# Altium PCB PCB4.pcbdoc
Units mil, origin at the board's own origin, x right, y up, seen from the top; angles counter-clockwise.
Board outline 3707.89 x 4491.52 mil, 2 copper layers (Top Layer, Bottom Layer); 62 components, 49 nets, 252 pads, 122 vias.
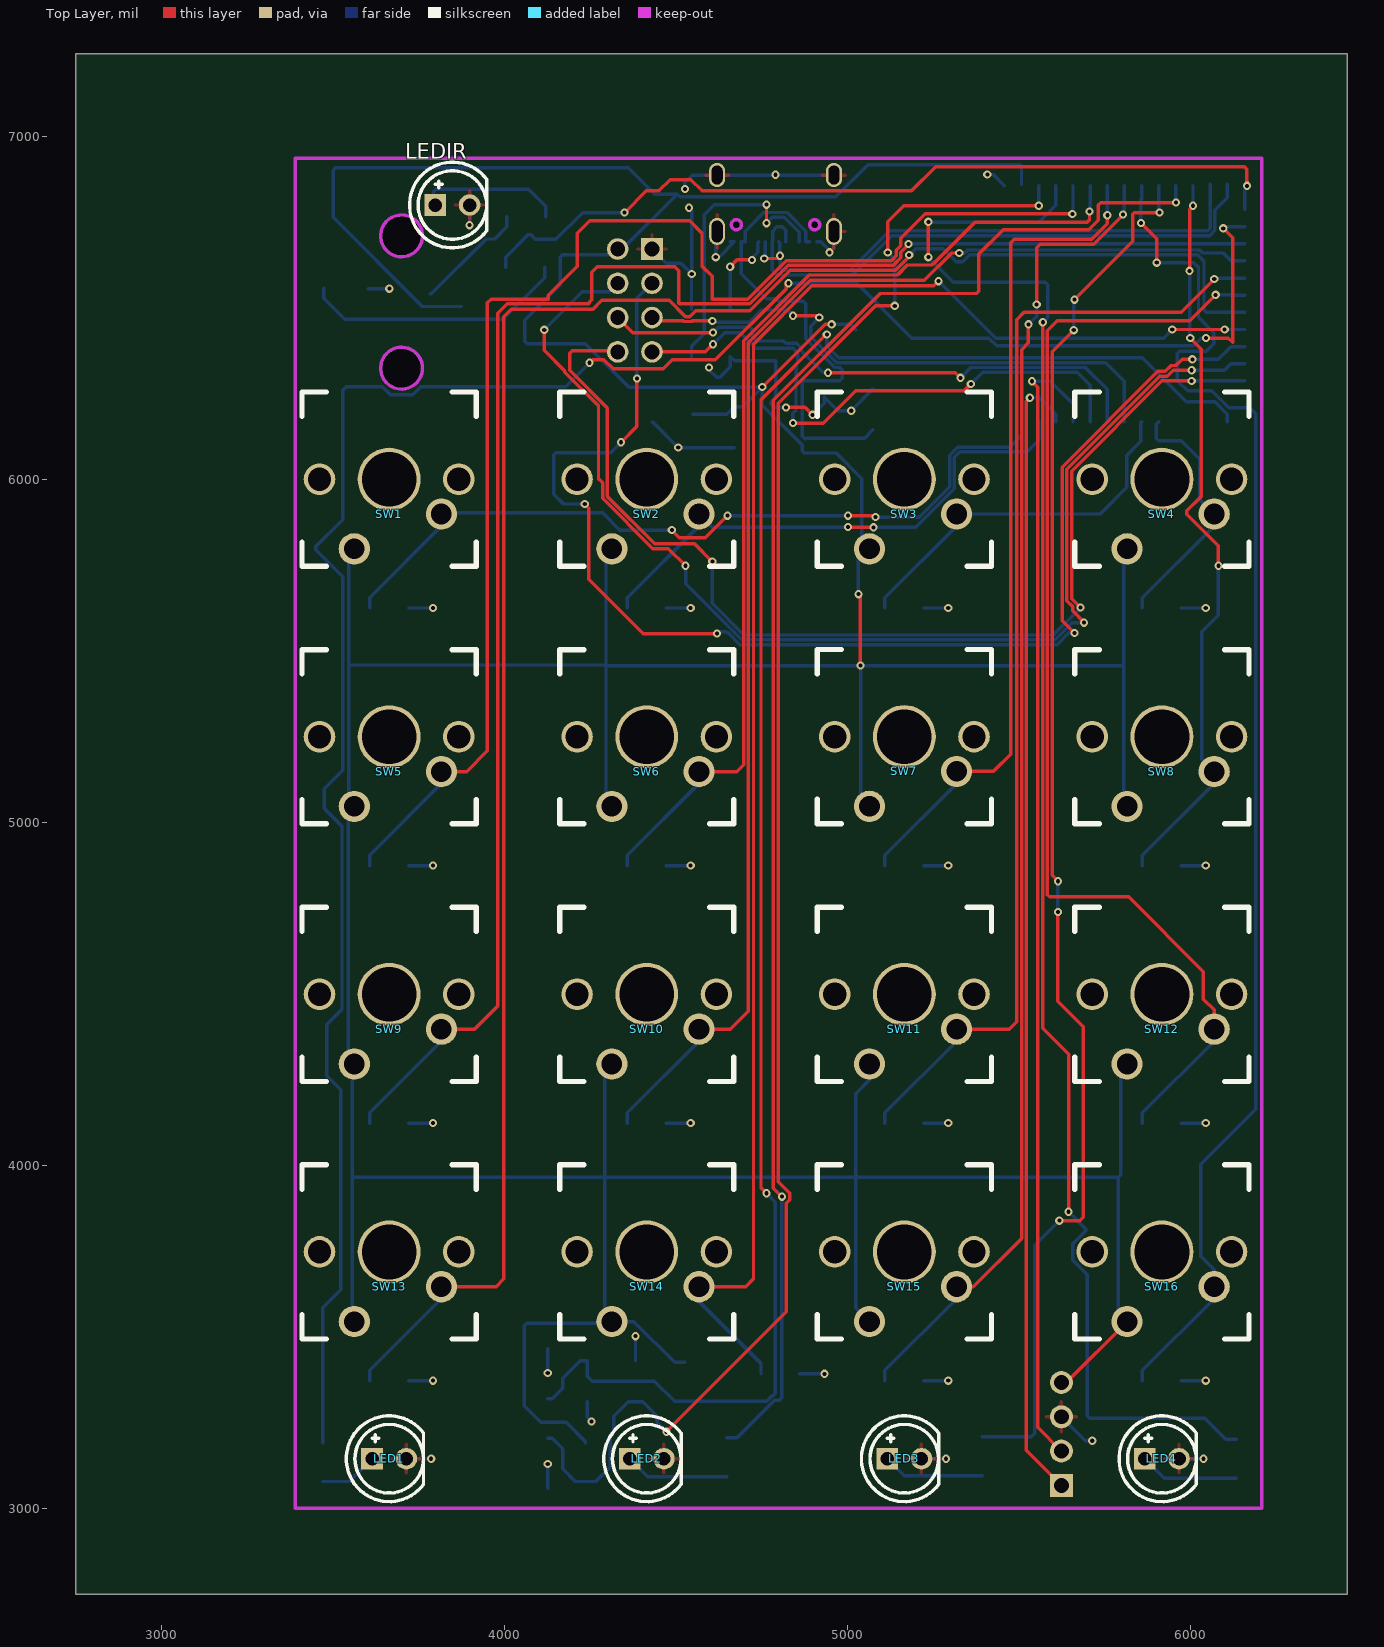
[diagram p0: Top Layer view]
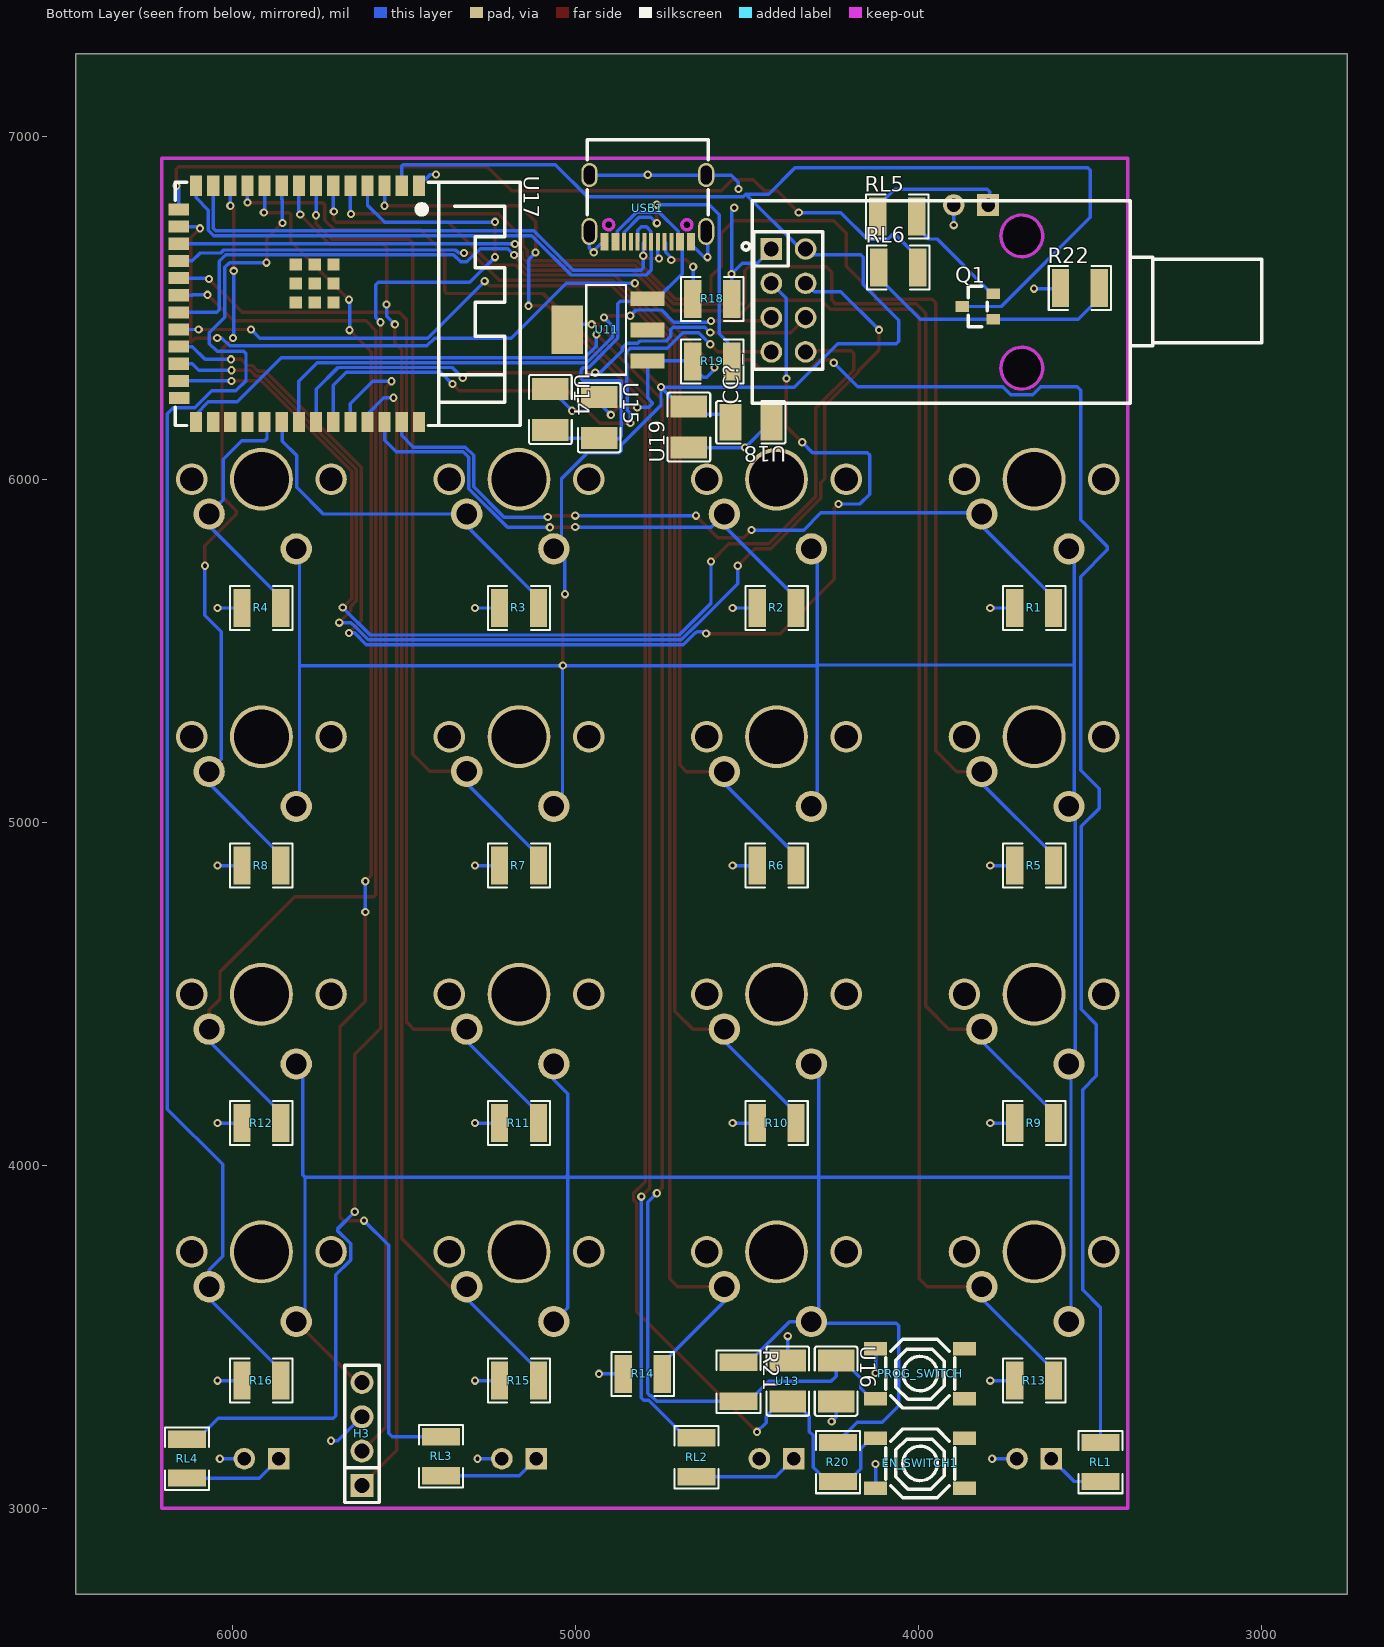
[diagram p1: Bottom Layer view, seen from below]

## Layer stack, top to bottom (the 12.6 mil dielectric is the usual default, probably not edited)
Top Layer: signal copper (thickness not stored)
Dielectric: dielectric 12.6, FR-4, Dk 4.8
Bottom Layer: signal copper (thickness not stored)

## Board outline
6457.89,2750 2750,2750 2750,7241.52 6457.89,7241.52

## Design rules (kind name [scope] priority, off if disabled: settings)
Clearance copperThickness1oz [All] p1: gap=7 ignorepadtopadclearanceinfootprint=FALSE except(4: Track-Track; 6: Track-SMDPad SMDPad-SMDPad Track-THPad SMDPad-THPad THPad-THPad Track-Via SMDPad-Via THPad-Via Via-Via Track-Fill SMDPad-Fill THPad-Fill Via-Fill Fill-Fill SMDPad-Region THPad-Region Via-Region Fill-Region Region-Region Track-Poly SMDPad-Poly THPad-Poly Via-Poly Fill-Poly Poly-Poly Track-Text SMDPad-Text THPad-Text Via-Text Fill-Text Region-Text Poly-Text Text-Text Track-Hole SMDPad-Hole THPad-Hole Via-Hole Fill-Hole Region-Hole Poly-Hole Text-Hole; 11.8: Track-Region Region-Poly Track-Sheet SMDPad-Sheet THPad-Sheet Via-Sheet Fill-Sheet Region-Sheet Poly-Sheet Text-Sheet Sheet-Hole)
Clearance copperThickness2oz [All] p1: gap=7 ignorepadtopadclearanceinfootprint=FALSE except(6: Track-SMDPad SMDPad-SMDPad Track-THPad SMDPad-THPad THPad-THPad Track-Via SMDPad-Via THPad-Via Via-Via Track-Fill SMDPad-Fill THPad-Fill Via-Fill Fill-Fill SMDPad-Region THPad-Region Via-Region Fill-Region Region-Region Track-Poly SMDPad-Poly THPad-Poly Via-Poly Fill-Poly Poly-Poly Track-Text SMDPad-Text THPad-Text Via-Text Fill-Text Region-Text Poly-Text Text-Text Track-Hole SMDPad-Hole THPad-Hole Via-Hole Fill-Hole Region-Hole Poly-Hole Text-Hole; 8: Track-Track; 11.8: Track-Region Region-Poly Track-Sheet SMDPad-Sheet THPad-Sheet Via-Sheet Fill-Sheet Region-Sheet Poly-Sheet Text-Sheet Sheet-Hole)
DiffPairsRouting differentialPair [All] p1: maxuncoupledlength=10 maxlimit=6 mostfreqgap=6 toplayer_minwidth=5 toplayer_prefwidth=10 toplayer_maxwidth=100 bottomlayer_minwidth=5 bottomlayer_prefwidth=10 bottomlayer_maxwidth=100
PasteMaskExpansion pasteMaskExpansion [All] p1:
PlaneConnect innerPlane [All] p1: planeconnectstyle=Relief reliefexpansion=20 reliefentries=4 reliefconductorwidth=10 reliefairgap=10
PolygonConnect copperRegion [All] p1: connectstyle=Relief reliefentries=4 reliefconductorwidth=10 polygonreliefangle="90 Angle" airgapwidth=10
RoutingVias viaSize [All] p1: viastyle="Through Hole" holewidth=12.0078 minholewidth=11.811 maxholewidth=248.0314 width=24.0158 minwidth=19.685 maxwidth=393.7008
SolderMaskExpansion solderMaskExpansion [All] p1: useseparateexpansions=TRUE expansion=2 expansionbottom=2
Width copperThickness1oz [All] p1: maxlimit=100 minlimit=5 preferedwidth=10
Width copperThickness2oz [All] p1: maxlimit=100 minlimit=8 preferedwidth=10

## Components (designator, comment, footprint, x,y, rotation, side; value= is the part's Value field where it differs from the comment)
CC?_ "CC1101 Module" CC1101-BOARS 3949.53,6520.97 r90 bottom
EN_SWITCH1 "TS-1187A-B-A-B" SW-SMD_4P-L5.1-W5.1-P3.70-LS6.5-TL-2 3995.89,3130.97 r180 bottom
H3 "HDR-M_2.54_1x4P" HDR-TH_4P-P2.54-V-M 5623.89,3216.97 r90 bottom
LED1 "LED_TH-R_5mm" LED-TH_BD5.8-P2.54-FD 3663.48,3144.65 r0 top
LED2 "LED_TH-R_5mm" LED-TH_BD5.8-P2.54-FD 4414.66,3144.65 r0 top
LED3 "LED_TH-R_5mm" LED-TH_BD5.8-P2.54-FD 5165.84,3144.65 r0 top
LED4 "LED_TH-R_5mm" LED-TH_BD5.8-P2.54-FD 5917.02,3144.65 r0 top
LEDIR "LED_TH-R_5mm" LED-TH_BD5.8-P2.54-FD 3847.89,6800.97 r0 top
PROG_SWITCH "TS-1187A-B-A-B" SW-SMD_4P-L5.1-W5.1-P3.70-LS6.5-TL-2 3995.89,3392.97 r180 bottom
Q1 "S8050_NPN" SOT-23_L2.9-W1.3-P1.90-LS2.4-BR 3827.89,6504.97 r180 bottom
R1 "1210W2F1022T5E" R1210 3663.48,5625.79 r180 bottom
R2 "1210W2F1022T5E" R1210 4414.66,5625.79 r180 bottom
R3 "1210W2F1022T5E" R1210 5165.84,5625.79 r180 bottom
R4 "1210W2F1022T5E" R1210 5917.02,5625.79 r180 bottom
R5 "1210W2F1022T5E" R1210 3663.48,4874.61 r180 bottom
R6 "1210W2F1022T5E" R1210 4414.66,4874.61 r180 bottom
R7 "1210W2F1022T5E" R1210 5165.84,4874.61 r180 bottom
R8 "1210W2F1022T5E" R1210 5917.02,4874.61 r180 bottom
R9 "1210W2F1022T5E" R1210 3663.48,4123.43 r180 bottom
R10 "1210W2F1022T5E" R1210 4414.66,4123.43 r180 bottom
R11 "1210W2F1022T5E" R1210 5165.84,4123.43 r180 bottom
R12 "1210W2F1022T5E" R1210 5917.02,4123.43 r180 bottom
R13 "1210W2F1022T5E" R1210 3663.48,3372.24 r180 bottom
R14 "1210W2F1022T5E" R1210 4804.66,3392.24 r180 bottom
R15 "1210W2F1022T5E" R1210 5165.84,3372.24 r180 bottom
R16 "1210W2F1022T5E" R1210 5917.02,3372.24 r180 bottom
R18 "SCR1210J5K1" R1210 4601.89,6526.97 r0 bottom
R19 "SCR1210J5K1" R1210 4601.89,6344.97 r180 bottom
R20 "1210W2F1022T5E" R1210 4235.89,3134.97 r90 bottom
R21 "1210W2F1022T5E" R1210 4525.89,3368.97 r270 bottom
R22 "1210W2F1022T5E" R1210 3529.89,6558.97 r180 bottom
RL1 "RTT12331JTP" R1210 3469.89,3134.97 r90 bottom
RL2 "RTT12331JTP" R1210 4647.89,3148.97 r90 bottom
RL3 "RTT12331JTP" R1210 5393.1,3152.12 r90 bottom
RL4 "RTT12331JTP" R1210 6133.89,3144.97 r90 bottom
RL5 "RTT12331JTP" R1210 4062.88,6767.19 r180 bottom
RL6 "RTT12331JTP" R1210 4059.89,6618.97 r180 bottom
SW1 "CHERRY-MX-LED" CHERRYMX 3663.48,6001.38 r0 top
SW2 "CHERRY-MX-LED" CHERRYMX 4414.66,6001.38 r0 top
SW3 "CHERRY-MX-LED" CHERRYMX 5165.84,6001.38 r0 top
SW4 "CHERRY-MX-LED" CHERRYMX 5917.02,6001.38 r0 top
SW5 "CHERRY-MX-LED" CHERRYMX 3663.48,5250.2 r0 top
SW6 "CHERRY-MX-LED" CHERRYMX 4414.66,5250.2 r0 top
SW7 "CHERRY-MX-LED" CHERRYMX 5165.84,5250.59 r0 top
SW8 "CHERRY-MX-LED" CHERRYMX 5917.02,5250.2 r0 top
SW9 "CHERRY-MX-LED" CHERRYMX 3663.48,4499.02 r0 top
SW10 "CHERRY-MX-LED" CHERRYMX 4414.66,4499.02 r0 top
SW11 "CHERRY-MX-LED" CHERRYMX 5165.84,4499.02 r0 top
SW12 "CHERRY-MX-LED" CHERRYMX 5917.02,4499.02 r0 top
SW13 "CHERRY-MX-LED" CHERRYMX 3663.48,3747.83 r0 top
SW14 "CHERRY-MX-LED" CHERRYMX 4414.66,3747.83 r0 top
SW15 "CHERRY-MX-LED" CHERRYMX 5165.84,3747.83 r0 top
SW16 "CHERRY-MX-LED" CHERRYMX 5917.02,3747.83 r0 top
U11 "AMS1117-3.3_C6186" SOT-223-3_L6.5-W3.4-P2.30-LS7.0-BR 4907.78,6436.97 r180 bottom
U13 "CC1210KKX7R9BB105" C1210 4381.89,3370.97 r90 bottom
U14 "CC1210KKX7R9BB105" C1210 5074.15,6204.71 r270 bottom
U15 "CC1210KKX7R9BB105" C1210 4932.15,6180.71 r270 bottom
U16 "CC1210KKX7R9BB105" C1210 4241.08,3370.76 r270 bottom
U17 "ESP32-S3-WROOM-1-N8R8" WIRELM-SMD_ESP32-S3-WROOM-1 5807.89,6512.97 r270 bottom
U18 "CC1210KKX7R9BB105" C1210 4489.63,6167.23 r0 bottom
U19 "CC1210KKX7R9BB105" C1210 4670.1,6153.26 r90 bottom
USB1 "USB-TYPE-C-018" USB-C_SMD-TYPE-C-31-M-12 4790.25,6790.97 r0 bottom

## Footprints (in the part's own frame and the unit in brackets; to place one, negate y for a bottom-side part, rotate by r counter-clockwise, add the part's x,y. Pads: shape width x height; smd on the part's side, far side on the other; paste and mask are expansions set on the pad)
C1210 [mm]
  rect 1.635x2.7 smd: 1(-1.517,0) 2(1.517,0)
  silkscreen extent -2.56,-1.58 2.56,1.58
CC1101-BOARS [mm]
  rect 1.6x1.6 hole 1.1: 1(3.856,12.203)
  round 1.6 hole 1.1: 2(3.856,9.663) 3(1.316,12.203) 4(1.316,9.663) 5(-1.224,12.203) 6(-1.224,9.663) 7(-3.764,12.203) 8(-3.764,9.663)
  Multi-Layer board cut-out: -4.974,-4.8 -4.301,-4.954 -3.762,-5.384 -3.463,-6.005 -3.463,-6.695 -3.762,-7.317 -4.302,-7.747 -4.974,-7.9 -4.974,-7.9 -5.647,-7.747 -6.186,-7.317 -6.485,-6.695 -6.485,-6.005 -6.186,-5.384 -5.647,-4.954 -4.974,-4.8
  Multi-Layer board cut-out: 4.826,-4.8 5.499,-4.954 6.038,-5.384 6.337,-6.005 6.337,-6.695 6.038,-7.317 5.499,-7.747 4.826,-7.9 4.826,-7.9 4.154,-7.747 3.614,-7.317 3.315,-6.695 3.315,-6.005 3.614,-5.384 4.154,-4.954 4.826,-4.8
  Multi-Layer keep-out circle w0.254: c-4.974,-6.35 r1.55
  Multi-Layer keep-out circle w0.254: c4.826,-6.35 r1.55
  silkscreen extent -7.57,-24.12 7.43,14.36
CHERRYMX [mil]
  round 91.4 hole 60: 1(-101.6,-203.2) 2(152.4,-101.6)
  round 92.1 hole 68: 3(203.2,0) 4(-203.2,0)
  round 183.5 hole 159.6: 5(0,0)
  silkscreen extent -254,-254 254,254
HDR-TH_4P-P2.54-V-M [mm]
  rect 1.7x1.7 hole 1.1: 1(-3.81,0)
  round 1.7 hole 1.1: 2(-1.27,0) 3(1.27,0) 4(3.81,0)
  silkscreen extent -5.08,-1.27 5.08,1.27
LED-TH_BD5.8-P2.54-FD [mm]
  rect 1.6x1.6 hole 1: 1(-1.27,0)
  round 1.6 hole 1: 2(1.27,0)
  silkscreen extent -3.17,-3.17 2.54,3.17
R1210 [mil]
  rect 50.49x110.55 smd: 1(-56.74,0) 2(56.74,0)
  silkscreen extent -91,-64 91,64
SOT-23_L2.9-W1.3-P1.90-LS2.4-BR [mm]
  rect 1x0.8 smd: 1(1.15,-0.95) 2(1.15,0.95) 3(-1.15,0)
  silkscreen extent -0.7,-1.5 0.7,1.5
SOT-223-3_L6.5-W3.4-P2.30-LS7.0-BR [mm]
  rect 2.5x1.1 smd: 1(2.97,-2.3) 2(2.97,0) 3(2.97,2.3)
  rect 2.34x3.6 smd: 4(-2.97,0)
  silkscreen extent -1.57,-3.33 1.37,3.33
SW-SMD_4P-L5.1-W5.1-P3.70-LS6.5-TL-2 [mm]
  rect 1.7x1 smd: 1(-3.3,1.85) 2(3.3,1.85) 3(-3.3,-1.85) 4(3.3,-1.85)
  silkscreen extent -2.55,-2.55 2.55,2.55
USB-C_SMD-TYPE-C-31-M-12 [mm]
  oval 1.2x2 hole 0.8 slot 1.6 at 90 deg: 0(-4.325,1.706) 1(4.325,1.706)
  oval 1.2x1.8 hole 0.8 slot 1.4 at 90 deg: 2(4.325,-2.474) 3(-4.325,-2.474)
  rect 0.3x1.3 smd: A1(-3.35,2.474) A4(-2.55,2.474) A5(-1.25,2.474) A6(-0.25,2.474) A7(0.25,2.474) A8(1.25,2.474) A9(2.55,2.474) A12(3.35,2.474) B1(3.05,2.474) B4(2.25,2.474) B5(1.75,2.474) B6(0.75,2.474) B7(-0.75,2.474) B8(-1.75,2.474) B9(-2.25,2.474) B12(-3.05,2.474)
  Multi-Layer board cut-out: -2.525,1.206 -2.577,1.02 -2.714,0.884 -2.9,0.835 -3.086,0.884 -3.223,1.02 -3.275,1.206 -3.275,1.206 -3.223,1.391 -3.086,1.527 -2.9,1.577 -2.714,1.527 -2.577,1.391 -2.525,1.206
  Multi-Layer board cut-out: 3.275,1.206 3.223,1.02 3.086,0.884 2.9,0.835 2.714,0.884 2.577,1.02 2.525,1.206 2.525,1.206 2.577,1.391 2.714,1.527 2.9,1.577 3.086,1.527 3.223,1.391 3.275,1.206
  Multi-Layer keep-out circle w0.254: c-2.9,1.206 r0.375
  Multi-Layer keep-out circle w0.254: c2.9,1.206 r0.375
  silkscreen extent -4.47,-5.09 4.47,0.49
WIRELM-SMD_ESP32-S3-WROOM-1 [mm]
  rect 1.5x0.9 smd: 1(-8.75,8.895) 2(-8.75,7.625) 3(-8.75,6.355) 4(-8.75,5.085) 5(-8.75,3.815) 6(-8.75,2.545) 7(-8.75,1.275) 8(-8.75,0.005) 9(-8.75,-1.265) 10(-8.75,-2.535) 11(-8.75,-3.805) 12(-8.75,-5.075) 13(-8.75,-6.345) 14(-8.75,-7.615) 27(8.75,-7.615) 28(8.75,-6.345) 29(8.75,-5.075) 30(8.75,-3.805) 31(8.75,-2.535) 32(8.75,-1.265) 33(8.75,0.005) 34(8.75,1.275) 35(8.75,2.545) 36(8.75,3.815) 37(8.75,5.085) 38(8.75,6.355) 39(8.75,7.625) 40(8.75,8.895)
  rect 0.9x1.5 smd: 15(-6.985,-8.895) 16(-5.715,-8.895) 17(-4.445,-8.895) 18(-3.175,-8.895) 19(-1.905,-8.895) 20(-0.635,-8.895) 21(0.635,-8.895) 22(1.905,-8.895) 23(3.175,-8.895) 24(4.445,-8.895) 25(5.715,-8.895) 26(6.985,-8.865)
  rect 0.9x0.9 smd: 41(-2.9,-0.225) 41(-2.9,1.175) 41(-2.9,2.575) 41(-1.5,-0.225) 41(-1.5,1.175) 41(-1.5,2.575) 41(-0.1,-0.225) 41(-0.1,1.175) 41(-0.1,2.575)
  silkscreen extent -9,-9.14 9.02,16.39

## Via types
v1: diameter 24.02, hole 12.01, Top Layer to Bottom Layer, 122 vias

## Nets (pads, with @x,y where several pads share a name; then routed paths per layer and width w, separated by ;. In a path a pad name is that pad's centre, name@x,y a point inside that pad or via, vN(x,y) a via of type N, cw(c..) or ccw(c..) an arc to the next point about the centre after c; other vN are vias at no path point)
3.3V: CC?_.2 H3.4 Q1.3 R20.2 R21.1 SW1.1 SW2.1 SW3.1 SW4.1 SW5.1 SW6.1 SW7.1 SW8.1 SW9.1 SW10.1 SW11.1 SW12.1 SW13.1 SW14.1 SW15.1 SW16.1 U11.4 U17.2 U18.2 U19.2 | length 18106.2
  Top Layer w10: v1(4751.67,6269.9) 4934.74,6452.97 v1(4953.89,6452.97) ; v1(5031.89,5666.02) 5037.89,5660.02 v1(5037.89,5457.75) ; H3.4 5637.76,3366.97 SW16.1
  Bottom Layer w10: SW13.1 3555.89,3550.63 3555.89,3966.07 ; SW1.1 3545.89,5782.19 3545.89,5460.97 ; Q1.3 3759.89,6504.97 3499.89,6764.97 3499.89,6902.97 3506.96,6910.04 4360.82,6910.04 4437.89,6832.97 4503.89,6832.97 ; R20.2 4235.89,3194.97 4179.89,3250.97 4105.89,3250.97 4057.89,3298.97 4057.89,3532.97 4064.96,3540.04 4308.47,3540.04 SW14.1 ; SW10.1 4291.57,4274.32 4291.57,3966.07 ; SW6.1 4295.89,5064.17 4295.89,5460.97 ; SW2.1 4295.89,5781.01 4295.89,5460.97 ; R21.1 4495.86,3425.71 4376.93,3544.63 SW14.1 ; U18.2@4549.37,6191.23 4648.33,6191.23 U19.2 4694.77,6213 v1(4751.67,6269.9) ; v1(4953.89,6452.97) 5008.71,6452.97 U11.4 ; v1@5031.89,5457.9 4298.96,5457.9 4295.89,5460.97 ; v1(5031.89,5666.02) 5031.89,5765.83 SW3.1 5041.89,5820.53 5041.89,6002.79 4966.88,6077.8 4874.45,6077.8 4868.02,6084.23 4868.02,6101.02 4751.67,6217.37 v1(4751.67,6269.9) ; SW15.1 5023.89,3584.99 5023.89,3966.07 4291.57,3966.07 ; SW11.1 5064.24,4249.32 5023.89,4208.97 5023.89,3973.14 5030.96,3966.07 5789.89,3966.07 ; SW7.1 5038.96,5072.67 5038.96,5457.9 5801.89,5457.9 5805.89,5461.9 ; U17.2@5507.69,6861.46 5507.69,6915.16 5503.89,6918.97 5059.89,6918.97 4965.95,6825.03 4511.83,6825.03 4503.89,6832.97 ; SW16.1 5789.89,3570.17 5789.89,3966.07 ; SW12.1 5796.96,4277.35 5796.96,3973.14 5789.89,3966.07 ; SW8.1 5805.89,5056.53 5805.89,5461.9 ; SW4.1@5815.89,5798.18 5805.89,5788.18 5805.89,5461.9 ; 3545.89,5460.97 3545.89,5062.99 SW5.1 3543.89,5029.01 3543.89,4313.81 SW9.1 3555.89,4289.83 3555.89,3966.07 ; 3545.89,5460.97 3547.4,5459.46 4294.38,5459.46 4295.89,5460.97 ; 3555.89,3966.07 4291.57,3966.07 ; 4291.57,3966.07 4291.57,3566.13 SW14.1 ; 4503.89,6832.97 4343.7,6672.78 CC?_.2 4313.22,6656.04 4168.96,6656.04 4161.89,6648.97 4161.89,6568.17 4058.82,6465.1 4058.82,6404.04 4065.89,6396.97 4235.89,6396.97 4362.96,6269.9 v1(4751.67,6269.9)
5V: U11.3 U14.2 U15.2 USB1.A4 USB1.A9 USB1.B4 USB1.B9 | length 1396.4
  Bottom Layer w10: USB1.A9 USB1.B4 4878.83,6724.44 4824.22,6779.05 4756.28,6779.05 4701.67,6724.44 USB1.B9 USB1.A4 4689.86,6600.95 4763.3,6527.52 U11.3 4798.34,6520.04 4870.82,6520.04 4877.89,6512.97 4877.89,6413.09 4878.88,6412.1 4878.88,6410.69 4962.49,6327.09 4977.77,6327.09 4984.96,6319.9 4984.96,6296.02 4977.89,6288.95 4868.02,6288.95 4868.02,6126.97 4875.09,6119.9 4878.96,6119.9 4880.03,6120.97 U15.2 5050.15,6120.97 U14.2
$1N17024: LED1.1 RL1.1 | length 171.1
  Bottom Layer w10: RL1.1 3547.06,3078.23 LED1.1
$1N17244: LED2.1 RL2.1 | length 304.9
  Bottom Layer w10: LED2.1 4417.09,3092.23 RL2.1
$1N17270: LED3.1 RL3.1 | length 297.7
  Bottom Layer w10: LED3.1 5165.12,3095.38 RL3.1
$1N17296: LED4.1 RL4.1 | length 290.2
  Bottom Layer w10: LED4.1 5923.45,3088.23 RL4.1
$1N41929: 
$1N42156: R19.2 USB1.B5 | length 825.7
  Top Layer w10: v1(4763.89,6747.98) v1(4763.89,6802.04)
  Bottom Layer w10: R19.2@4545.15,6358.97 4545.15,6389 4581.89,6425.74 4581.89,6772.97 4610.96,6802.04 v1(4763.89,6802.04) ; v1(4763.89,6747.98) 4780.95,6765.03 4815.83,6765.03 4859.15,6721.71 USB1.B5
$1N52929: LEDIR.1 RL5.1 | length 421.4
  Bottom Layer w10: LEDIR.1 3797.89,6824.83 3792.82,6829.9 3792.82,6839.9 3799.89,6846.97 4069.87,6846.97 4119.62,6797.22 RL5.1
$1N52957: Q1.2 RL5.2 | length 334.2
  Bottom Layer w10: Q1.2 3786.55,6542.37 3946.1,6701.92 3970.89,6701.92 4006.14,6737.16 RL5.2
$1N53158: Q1.1 R22.2 RL6.1 | length 779.2
  Bottom Layer w10: R22.2 3473.15,6528.94 3534.52,6467.57 Q1.1 3995.26,6467.57 4116.63,6588.94 RL6.1
EN: EN_SWITCH1.1 R20.1 U13.1 U17.3 | length 5051.1
  Top Layer w10: v1(4471.89,3222.97) 4821.89,3572.97 4821.89,3889.38 4831.95,3899.44 4831.95,3918.49 4797.91,3952.54 4797.91,6222.98 5081.89,6506.97 v1(5137.89,6506.97) ; v1(5117.49,6662.51) 5117.49,6752.57 5163.89,6798.97 v1(5557.89,6798.97)
  Bottom Layer w10: EN_SWITCH1.1 4139.59,3203.81 4169.27,3174.13 4169.27,3114.82 4205.86,3078.23 R20.1 4265.92,3078.23 4307.89,3120.2 4307.89,3212.97 4318.74,3223.82 4318.74,3269.05 4360.93,3311.23 U13.1 4402.85,3311.23 4445.04,3269.05 4445.04,3249.82 v1(4471.89,3222.97) ; v1(5117.49,6662.51) 5137.89,6642.1 v1(5137.89,6506.97) ; U17.3 5557.89,6857.26 v1(5557.89,6798.97)
GND: CC?_.1 EN_SWITCH1.3 H3.3 LED1.2 LED2.2 LED3.2 LED4.2 LEDIR.2 PROG_SWITCH.1 R1.1 R2.1 R3.1 R4.1 R5.1 R6.1 R7.1 R8.1 R9.1 R10.1 R11.1 R12.1 R13.1 R14.1 R15.1 R16.1 R18.1 R19.1 R22.1 U11.1 U13.2 U14.1 U15.1 U16.2 U17.1 U18.1 U19.1 USB1.0 USB1.1 USB1.2 USB1.3 USB1.A1 USB1.A12 USB1.B1 USB1.B12 | length 4168.7
  Top Layer w10: v1(4820.9,6210.6) 4876.26,6210.6 v1(4897.89,6188.97)
  Bottom Layer w10: R22.1@3602.63,6556.97 v1(3663.89,6556.97) ; LED1.2 v1(3785.89,3144.65) ; R13.1 v1(3791.53,3372.24) ; R9.1 v1(3791.53,4123.43) ; R5.1 v1(3791.53,4874.61) ; R1.1 v1(3791.53,5625.79) ; v1(3897.89,6742.15) LEDIR.2 ; EN_SWITCH1.3 v1(4125.81,3129.43) ; v1(4125.81,3394.5) PROG_SWITCH.1 ; U16.2 4241.08,3265.78 v1(4253.89,3252.97) ; U13.2 v1(4381.89,3502.02) ; U18.1 4432.93,6167.23 v1(4506.63,6093.52) U19.1 ; CC?_.1 4471.45,6631.29 4514.58,6631.29 v1(4545.89,6599.98) ; R10.1 v1(4542.71,4123.43) ; R6.1 v1(4542.71,4874.61) ; R2.1 v1(4542.71,5625.79) ; v1(4525.89,6848.02) 4525.89,6866.97 4547.3,6888.37 USB1.3 4789.28,6888.37 v1(4790.25,6889.34) 4791.22,6888.37 USB1.2 ; v1(4537.89,6792.97) 4545.89,6784.97 v1(4545.89,6599.98) ; R18.1@4545.15,6496.97 4545.15,6599.24 v1(4545.89,6599.98) ; v1(4595.94,6326.97) 4595.94,6321.14 4618.39,6298.69 4628.39,6298.69 4658.63,6328.94 4658.63,6358.97 4671.18,6346.42 U11.1 4790.86,6238.61 4776.9,6224.65 4776.9,6221.96 4787.89,6210.97 4820.53,6210.97 v1(4820.9,6210.6) ; USB1.0 4615.89,6719.73 v1(4615.89,6648.97) 4625.58,6648.97 USB1.B12 USB1.A1 ; R14.1 v1(4932.71,3392.24) ; v1(4897.89,6188.97) 4932.15,6223.23 U15.1 4971.63,6200.97 v1(5011.03,6200.97) 5011.03,6201.32 U14.1 ; USB1.B1 USB1.A12 4947.89,6667.81 v1(4947.89,6662.97) 4960.53,6675.61 USB1.1 ; LED3.2 v1(5287.15,3144.65) ; R15.1 v1(5293.89,3372.24) ; R11.1 v1(5293.89,4123.43) ; R7.1 v1(5293.89,4874.61) ; R3.1 v1(5293.89,5625.79) ; v1(5407.89,6889.98) 5425.18,6889.98 U17.1 ; H3.3 5693.89,3196.97 v1(5713.89,3196.97) ; LED4.2 v1(6038.33,3144.65) ; R16.1 v1(6045.07,3372.24) ; R12.1 v1(6045.07,4123.43) ; R8.1 v1(6045.07,4874.61) ; R4.1 v1(6045.07,5625.79)
IO0: PROG_SWITCH.3 R21.2 U16.1 U17.27 | length 5304.6
  Top Layer w10: v1(4763.89,3918.97) 4747.89,3934.97 4747.89,6233.61 4937.25,6422.97 v1(4939.89,6422.97)
  Bottom Layer w10: PROG_SWITCH.3 4139.59,3320.13 4169.27,3349.81 4169.27,3379.65 4220.11,3430.49 U16.1 4241.08,3385.78 4255.89,3370.97 4437.12,3370.97 4495.86,3312.23 R21.2 4764.62,3312.23 4781.37,3328.98 4783.91,3328.98 4789.89,3334.97 4789.89,3892.97 v1(4763.89,3918.97) ; v1(4939.89,6422.97) 4939.89,6389.33 4974.1,6355.12 5859.74,6355.12 5987.89,6226.97 6071.89,6226.97 6107.69,6191.16 U17.27
IO1: R1.2 SW1.2 U17.39 | length 2303.4
  Top Layer w10: v1(4487.89,5852.97) 4509.89,5830.97 4585.89,5830.97 v1(4649.89,5894.97) ; v1(5001.89,5894.97) 5077.87,5894.97 v1(5081.87,5890.97)
  Bottom Layer w10: R1.2 3606.74,5655.82 3815.88,5864.96 SW1.2 3819.07,5902.97 4285.89,5902.97 4335.89,5852.97 v1(4487.89,5852.97) ; v1(4649.89,5894.97) v1(5001.89,5894.97) ; v1(5081.87,5890.97) 5209.45,5890.97 5297.87,5979.39 5297.87,6070.77 5322.08,6094.98 5473.73,6094.98 5507.69,6128.95 U17.39
IO2: R2.2 SW2.2 U17.38 | length 1579.9
  Top Layer w10: v1(5001.89,5861.78) 5075.08,5861.78 v1(5075.89,5860.97)
  Bottom Layer w10: R2.2 4357.92,5655.82 4567.06,5864.96 SW2.2 4605.27,5861.57 5001.68,5861.57 v1(5001.89,5861.78) ; v1(5075.89,5860.97) 5199.27,5860.97 5311.89,5973.59 5311.89,6064.97 5327.89,6080.97 5523.89,6080.97 5557.69,6114.77 U17.38
IO3: RL6.2 U17.15 | length 2463.9
  Top Layer w10: v1(4349.89,6778.97) 4412.88,6841.96 4449.89,6841.96 4482.9,6874.97 4543.36,6874.97 4576.37,6841.96 5186.88,6841.96 5257.89,6912.97 6157.89,6912.97 6164.96,6905.9 v1(6164.96,6856.97)
  Bottom Layer w10: RL6.2 4003.15,6649 4069.12,6714.97 4075.78,6714.97 4089.82,6700.93 4149.42,6700.93 4227.45,6778.97 v1(4349.89,6778.97) ; U17.15 6158.09,6850.09 v1(6164.96,6856.97)
IO4: RL4.2 U17.4 | length 4781.7
  Top Layer w10: v1(5235.89,6648.97) v1(5235.89,6751.98) ; 5568.95,6446.04 5568.95,4399.91 5644.82,4324.04 v1(5644.82,3864.97) ; v1@5569.89,6451.1 v1(5569.89,6458.97)
  Bottom Layer w10: v1(5235.89,6648.97) 5308.82,6576.04 5576.82,6576.04 5583.89,6568.97 5583.89,6472.97 v1(5569.89,6458.97) ; v1(5235.89,6751.98) 5236.9,6750.97 5557.89,6750.97 5607.69,6800.77 U17.4 ; v1(5644.82,3864.97) 5695.23,3814.56 5695.23,3809.9 5656.79,3771.46 5656.79,3724.21 5699.89,3681.11 5699.89,3270.04 5706.96,3262.97 6042.6,3262.97 6103.86,3201.71 RL4.2
IO5: R5.2 SW5.2 U17.5 | length 4092.5
  Top Layer w10: SW5.2 3889.52,5148.6 3949.89,5208.97 3949.89,6515.9 3960.67,6526.68 4127.04,6526.68 4127.04,6538.12 4211.89,6622.97 4211.89,6718.97 4247.89,6754.97 4539.89,6754.97 4575.89,6718.97 4575.89,6622.97 4605.89,6592.97 4605.89,6526.68 4709.44,6526.68 4821.76,6639 5128.46,6639 5141.96,6652.51 5141.96,6669.38 5154.9,6682.31 5154.9,6703.5 5226.37,6774.97 v1(5655.89,6774.97)
  Bottom Layer w10: R5.2 3606.74,4904.64 3815.88,5113.78 SW5.2 ; v1(5655.89,6774.97) 5657.69,6776.77 U17.5
IO6: R6.2 SW6.2 U17.6 | length 2991.3
  Top Layer w10: SW6.2 4677.52,5148.6 4696.93,5168.01 4696.93,6405.65 4888.23,6596.95 5145.87,6596.95 5174.9,6625.98 5245.41,6625.98 5248.41,6628.97 5249.89,6628.97 5371.89,6750.97 5698.86,6750.97 5705.89,6758 v1(5705.89,6782)
  Bottom Layer w10: R6.2 4357.92,4904.64 4567.06,5113.78 SW6.2 ; v1(5705.89,6782) 5707.69,6783.8 U17.6
IO7: R7.2 SW7.2 U17.7 | length 2447.2
  Top Layer w10: SW7.2 5425.91,5148.99 5475.89,5198.97 5475.89,6690.98 5485.89,6700.98 5712.08,6700.98 5757.89,6746.79 v1(5757.89,6770.97)
  Bottom Layer w10: R7.2 5109.1,4904.64 5318.24,5113.78 SW7.2 ; U17.7 5757.69,6771.16 v1(5757.89,6770.97)
IO8: R8.2 SW8.2 U17.12 | length 2173.9
  Top Layer w10: v1(5997.69,6608.97) 5997.69,6788.97 v1(6007.69,6798.97) ; v1(5999.69,6412.97) 6031.89,6380.77 6031.89,5950.97 5989.89,5908.97 5989.89,5898.97 6081.89,5806.97 v1@6081.89,5752.97
  Bottom Layer w10: R8.2 5860.28,4904.64 6069.42,5113.78 SW8.2 6033.89,5184.13 6033.89,5556.97 6081.89,5604.97 v1(6081.89,5748.97) ; v1(5997.69,6608.97) 5997.69,6414.97 v1(5999.69,6412.97) ; v1(6007.69,6798.97) U17.12
IO9: R9.2 SW9.2 U17.17 | length 5039.4
  Top Layer w10: SW9.2 3912.34,4397.42 3979.89,4464.97 3979.89,6484.97 4007.58,6512.66 4245.02,6512.66 4246.82,6514.46 4246.82,6517.9 4253.89,6524.97 4253.89,6604.97 4269.89,6620.97 4495.89,6620.97 4507.89,6608.97 4507.89,6514.89 4510.12,6512.66 4715.24,6512.66 4827.57,6624.98 5134.26,6624.98 5155.98,6646.7 5155.98,6663.57 5177.89,6685.48 v1(5177.89,6686.97)
  Bottom Layer w10: R9.2 3606.74,4153.45 3815.88,4362.59 SW9.2 ; v1(5177.89,6686.97) 5178.89,6687.97 U17.17
IO10: R10.2 SW10.2 U17.18 | length 4048.3
  Top Layer w10: SW10.2 4658.34,4397.42 4710.95,4450.03 4710.95,6399.85 4892.07,6580.97 5223.89,6580.97 5303.89,6660.97 v1(5325.89,6660.97)
  Bottom Layer w10: R10.2 4357.92,4153.45 4567.06,4362.59 SW10.2 ; v1(5325.89,6660.97) 5342.07,6660.97 5350.97,6669.86 6026.81,6669.86 6035.71,6660.97 6095.56,6660.97 6118.56,6637.97 U17.18
IO11: R11.2 SW11.2 U17.19 | length 3307.5
  Top Layer w10: SW11.2 5472.34,4397.42 5493.89,4418.97 5493.89,6466.97 5514.9,6487.98 5972.9,6487.98 v1(6069.89,6584.97)
  Bottom Layer w10: R11.2 5109.1,4153.45 5318.24,4362.59 SW11.2 ; v1(6069.89,6584.97) 6072.89,6587.97 U17.19
IO12: R12.2 SW12.2 U17.20 | length 3352.4
  Top Layer w10: SW12.2 6069.42,4453.43 6037.89,4484.97 6037.89,4564.97 5819.89,4782.97 5590.03,4782.97 5582.96,4790.04 5582.96,6434.04 5611.87,6462.95 5997.87,6462.95 v1(6073.89,6538.97)
  Bottom Layer w10: R12.2 5860.28,4153.45 6069.42,4362.59 SW12.2 ; v1(6073.89,6538.97) 6117.56,6538.97 6118.56,6537.97 U17.20
IO13: R13.2 SW13.2 U17.21 | length 5820.1
  Top Layer w10: SW13.2 3975.16,3646.23 3997.89,3668.97 3997.89,6474.97 4019.89,6496.97 4257.89,6496.97 4283.89,6522.97 4479.99,6522.97 4527.71,6475.26 4540.18,6475.26 4557.91,6492.98 4715.39,6492.98 4833.37,6610.97 5140.07,6610.97 5179.89,6650.79 v1(5179.89,6654.97)
  Bottom Layer w10: R13.2 3606.74,3402.27 3815.88,3611.41 SW13.2 ; v1(5179.89,6654.97) 5198.87,6673.95 5278.91,6673.95 5317.89,6634.97 5335.89,6634.97 5356.77,6655.85 6021.01,6655.85 6039.89,6636.97 6039.89,6495.04 6046.96,6487.97 U17.21
IO14: R14.2 SW14.2 U17.22 | length 4810.7
  Top Layer w10: SW14.2 4703.16,3646.23 4725.89,3668.97 4725.89,6394.97 4895.89,6564.97 5251.89,6564.97 v1(5265.89,6578.97) ; v1(5947.08,6437.97) v1(6100.09,6437.97)
  Bottom Layer w10: SW14.2 4567.06,3603.13 4747.92,3422.27 R14.2 ; v1(5265.89,6578.97) 5431.89,6412.97 5922.08,6412.97 v1(5947.08,6437.97) ; v1(6100.09,6437.97) U17.22
IO15: R15.2 SW15.2 U17.8 | length 3894.6
  Top Layer w10: SW15.2 5367.16,3646.23 5507.91,3786.98 5507.91,6378.99 5527.89,6398.98 v1(5527.89,6452.97) ; v1(5551.89,6510.97) 5551.89,6676.97 5561.89,6686.97 5717.89,6686.97 v1(5803.89,6772.97)
  Bottom Layer w10: R15.2 5109.1,3402.27 5318.24,3611.41 SW15.2 ; v1(5527.89,6452.97) 5551.89,6476.97 v1(5551.89,6510.97) ; v1(5803.89,6772.97) 5807.69,6776.77 U17.8
IO16: R16.2 SW16.2 U17.9 | length 4069
  Top Layer w10: v1(5855.89,6748.89) 5901.89,6702.89 v1(5901.89,6632.86)
  Bottom Layer w10: v1(5855.89,6748.89) 5855.89,6816.13 5857.69,6817.93 U17.9 ; R16.2 5860.28,3402.27 6069.42,3611.41 SW16.2 6069.42,3695.43 6029.89,3734.97 6029.89,4002.97 6191.08,4164.16 6191.08,6191.78 6173.59,6209.27 6111.89,6209.27 6062.19,6258.97 5991.89,6258.97 5961.89,6288.97 5961.89,6366.97 5968.96,6374.04 6046.02,6374.04 6068.88,6396.9 6068.88,6427.98 6023.71,6473.15 6023.71,6619.15 6010,6632.86 v1(5901.89,6632.86)
IO17: RL3.2 U17.10 | length 4100.4
  Top Layer w10: v1(5613.89,4738.97) 5613.89,4478.97 5687.89,4404.97 5687.89,3848.97 5677.89,3838.97 v1(5617.89,3838.97) ; v1(5613.89,4828.93) 5596.98,4845.84 5596.98,6373.05 v1(5659.89,6435.96) ; v1(5661.89,6524.97) 5831.89,6694.97 5831.89,6773.91 5836.95,6778.97 v1(5909.89,6778.97)
  Bottom Layer w10: RL3.2 5535.89,3208.86 5545.89,3218.86 5545.89,3766.97 v1(5617.89,3838.97) ; v1(5613.89,4738.97) v1(5613.89,4828.93) ; v1(5659.89,6435.96) 5659.89,6522.97 v1(5661.89,6524.97) ; U17.10 5907.69,6781.16 v1(5909.89,6778.97)
IO18: RL2.2 U17.11 | length 4680.1
  Top Layer w10: v1(4808.96,3908.97) 4783.89,3934.04 4783.89,6230.97 5095.89,6542.97 5375.89,6542.97 5382.96,6550.04 5382.96,6658.04 5453.89,6728.97 5703.89,6728.97 5731.89,6756.97 5731.89,6800.97 5738.96,6808.04 v1(5957.89,6808.04)
  Bottom Layer w10: RL2.2 4677.92,3205.71 4787.18,3314.97 4801.89,3314.97 4808.96,3322.04 v1(4808.96,3908.97) ; U17.11 5957.89,6857.26 v1(5957.89,6808.04)
IO19: U17.13 USB1.A7 USB1.B7 | length 1612.8
  Top Layer w10: v1(4757.42,6644.97) 4795.22,6644.97 v1(4803.4,6653.15)
  Bottom Layer w10: v1(4757.42,6644.97) 4760.72,6648.27 USB1.B7 ; USB1.A7 4802.89,6690.76 4802.89,6653.66 v1(4803.4,6653.15) 4803.4,6617.53 4809.96,6610.97 5007.89,6610.97 5122.82,6725.9 6050.62,6725.9 6057.69,6732.97 U17.13@6057.69,6861.46
IO20: U17.14 USB1.A6 USB1.B6 | length 1695.1
  Bottom Layer w10: USB1.B6 4819.89,6693.67 4819.89,6726.97 4809.89,6736.97 4793.91,6736.97 4781.89,6724.95 4781.89,6695.04 USB1.A6 4780.41,6611.5 4794.96,6596.95 5013.7,6596.95 5128.62,6711.88 6056.43,6711.88 6071.71,6727.16 6071.71,6785.95 6107.69,6821.93 U17.14@6107.69,6861.46
IO21: CC?_.3 U17.23 | length 3845.6
  Top Layer w10: v1(4233.89,5928.97) 4245.89,5916.97 4245.89,5708.97 4403.89,5550.97 v1(4619.89,5550.97) ; v1(4339.89,6108.97) 4385.89,6154.97 v1(4385.89,6294.97) ; v1(5661.89,5552.97) 5625.86,5589 5625.86,6036.58 5905.28,6316 5927.1,6316 5944.08,6332.98 5957.91,6332.98 5975.89,6350.97 v1(6005.89,6350.97)
  Bottom Layer w10: v1(4233.89,5928.97) 4171.89,5928.97 4142.82,5958.04 4142.82,6071.9 4149.89,6078.97 4309.89,6078.97 v1(4339.89,6108.97) ; v1(4385.89,6294.97) 4385.89,6528.71 CC?_.3 ; v1(4619.89,5550.97) 4625.89,5556.97 4645.89,5556.97 4649.89,5552.97 4652.25,5552.97 4686.28,5518.94 5611.5,5518.94 5645.53,5552.97 v1(5661.89,5552.97) ; v1(6005.89,6350.97) 6081.56,6350.97 6118.56,6387.97 U17.23
IO35: U17.28
IO36: U17.29
IO37: U17.30
IO38: R4.2 SW4.2 U17.31 | length 740.7
  Bottom Layer w10: R4.2 5860.28,5655.82 6069.42,5864.96 SW4.2 6027.89,5941.31 6027.89,6058.97 5973.89,6112.97 5907.89,6112.97 5900.82,6120.04 5900.82,6161.6 U17.31
IO39: R3.2 SW3.2 U17.32 | length 1097.9
  Bottom Layer w10: R3.2 5109.1,5655.82 5318.24,5864.96 SW3.2 5736.7,5899.78 5814.29,5977.37 5814.29,6070.44 5855.89,6112.04 5855.89,6166.67 U17.32
IO40: CC?_.5 U17.33 | length 1673.2
  Top Layer w10: CC?_.5 4439.77,6462.97 4520.96,6462.97 4521.9,6461.24 4545.98,6461.24 4547.71,6462.97 v1(4605.89,6462.97) ; v1(4841.43,6477.99) 4912.87,6477.99 v1(4917.89,6472.97)
  Bottom Layer w10: v1(4605.89,6462.97) 4609.89,6458.97 4713.89,6458.97 4749.8,6494.88 4824.54,6494.88 v1(4841.43,6477.99) ; v1(4917.89,6472.97) 4892.9,6447.98 4892.9,6416.5 4968.29,6341.1 5753.76,6341.1 5807.69,6287.16 U17.33
IO41: CC?_.6 U17.34 | length 1663.6
  Top Layer w10: CC?_.6 4373.77,6428.97 v1(4607.89,6428.97) ; v1(4943.38,6311.94) 5314.92,6311.94 v1(5329.89,6296.97)
  Bottom Layer w10: v1(4607.89,6428.97) 4623.87,6444.95 ; 4623.89,6444.95 4715.89,6444.95 4722.96,6437.88 4722.96,6417.9 4736.53,6404.33 4812.88,6404.33 4819.89,6397.32 4851.54,6397.32 4864.87,6383.99 4864.87,6376.35 4928.15,6313.07 4942.25,6313.07 v1(4943.38,6311.94) ; v1(5329.89,6296.97) 5360.01,6327.09 5693.77,6327.09 5757.69,6263.16 U17.34
IO42: CC?_.7 U17.35 | length 1733.7
  Top Layer w10: CC?_.7 4585.7,6372.78 v1(4607.89,6394.97) ; v1(4841.02,6165.05) 4929.98,6165.05 5023.89,6258.97 5339.89,6258.97 v1(5359.89,6278.97)
  Bottom Layer w10: v1(4607.89,6394.97) 4641.89,6428.97 4687.89,6428.97 4733.89,6382.97 4841.89,6382.97 4851.09,6373.77 4850.85,6370.54 4854.82,6366.58 4854.82,6341.9 4851.05,6338.13 4851.05,6274.9 4849.89,6273.73 4849.89,6202.97 4841.02,6194.1 v1(4841.02,6165.05) ; v1(5359.89,6278.97) 5393.99,6313.07 5669.79,6313.07 5707.69,6275.16 U17.35
IO45: U17.26
IO46: RL1.2 U17.16 | length 6505.4
  Top Layer w10: v1(4247.89,6340.97) 4256.88,6349.96 4289.44,6349.96 4316.43,6322.97 4462.66,6322.97 4489.65,6349.96 4614.88,6349.96 4820.98,6556.06 v1@4820.98,6575.88 ; v1(6045.89,6412.97) 6110.26,6412.97 6123.08,6400.16 6123.08,6705.78 v1(6095.89,6732.97)
  Bottom Layer w10: RL1.2 3469.89,3584.97 3521.89,3636.97 3521.89,4220.97 3481.89,4260.97 3481.89,4410.97 3525.89,4454.97 3525.89,4988.97 3473.89,5040.97 3473.89,5098.97 3527.89,5152.97 3527.89,5716.97 3449.89,5794.97 3449.89,5804.97 3527.89,5882.97 3527.89,6260.97 3537.89,6270.97 3643.62,6270.97 3667.29,6247.31 3731.77,6247.31 3755.43,6270.97 4177.89,6270.97 v1(4247.89,6340.97) ; v1(4827.89,6572.97) 5027.89,6572.97 5187.89,6412.97 5412.07,6412.97 5435.06,6389.98 6009.22,6389.98 6032.21,6412.97 v1(6045.89,6412.97) ; v1(6095.89,6732.97) 6100.89,6737.97 U17.16
IO47: CC?_.4 U17.24 | length 3572.5
  Top Layer w10: v1(4115.89,6436.97) 4115.89,6376.97 4175.87,6316.98 4175.87,6313.16 4273.89,6215.15 4273.89,6002.97 4285.87,5990.98 4285.87,5945.16 4432.08,5798.95 4477.91,5798.95 v1(4527.89,5748.97) ; v1(5689.89,5582.97) 5689.89,5584.45 5656.9,5617.44 5656.9,5630.14 5639.87,5647.16 5639.87,6030.77 5911.08,6301.98 5932.91,6301.98 5949.89,6318.97 v1(6003.89,6318.97)
  Bottom Layer w10: v1(4115.89,6436.97) 4226.82,6547.9 4305.07,6547.9 CC?_.4 ; v1(4527.89,5748.97) 4527.89,5696.97 4647.89,5576.97 4648.07,5576.97 4692.08,5532.95 5605.7,5532.95 5649.71,5576.97 5649.89,5576.97 5655.89,5582.97 v1(5689.89,5582.97) ; v1(6003.89,6318.97) 6099.56,6318.97 6118.56,6337.97 U17.24
IO48: CC?_.8 U17.25 | length 3281.8
  Top Layer w10: CC?_.8 4326.7,6376.04 4196.96,6376.04 4189.89,6368.97 4189.89,6318.97 4299.89,6208.97 4299.89,5950.97 4437.89,5812.97 4553.89,5812.97 v1(4605.89,5760.97) ; v1(5679.89,5626.97) 5653.89,5652.97 5653.89,6024.97 5916.89,6287.97 v1(6003.89,6287.97)
  Bottom Layer w10: v1(4605.89,5760.97) 4605.89,5638.97 4697.89,5546.97 5599.89,5546.97 v1(5679.89,5626.97) ; v1(6003.89,6287.97) U17.25
RX: H3.2 U17.36 | length 3355.4
  Top Layer w10: v1(5537.89,6286.97) 5554.88,6269.98 5554.88,3235.98 H3.2
  Bottom Layer w10: v1(5537.89,6286.97) 5591.89,6286.97 5657.69,6221.16 U17.36
TX: H3.1 U17.37 | length 3336.7
  Top Layer w10: v1(5531.89,6238.97) 5521.92,6229 5521.92,3168.94 H3.1
  Bottom Layer w10: v1(5531.89,6238.97) 5559.89,6238.97 5607.69,6191.16 U17.37
pads on no net: EN_SWITCH1.2 EN_SWITCH1.4 PROG_SWITCH.2 PROG_SWITCH.4 R18.2 SW1.3 SW1.4 SW1.5 SW2.3 SW2.4 SW2.5 SW3.3 SW3.4 SW3.5 SW4.3 SW4.4 SW4.5 SW5.3 SW5.4 SW5.5 SW6.3 SW6.4 SW6.5 SW7.3 SW7.4 SW7.5 SW8.3 SW8.4 SW8.5 SW9.3 SW9.4 SW9.5 SW10.3 SW10.4 SW10.5 SW11.3 SW11.4 SW11.5 SW12.3 SW12.4 SW12.5 SW13.3 SW13.4 SW13.5 SW14.3 SW14.4 SW14.5 SW15.3 SW15.4 SW15.5 SW16.3 SW16.4 SW16.5 U11.2 U17.40 U17.41 USB1.A5 USB1.A8 USB1.B8
copper on no net: | length 257.1
  Top Layer w10: v1(4657.89,6620.97) 4677.89,6640.97 v1(4721.89,6640.97)
  Bottom Layer w10: v1(4657.89,6620.97) 4657.89,6497.71 4658.63,6496.97 ; v1(4721.89,6640.97) 4721.89,6647.07 4738.24,6663.42 4738.24,6690.76 4741.04,6693.56

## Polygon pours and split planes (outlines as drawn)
GND on Top Layer (solid, remove dead copper): 3389.89,3000 6207.89,3000 6207.89,6936.97 3389.89,6936.97

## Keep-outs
Board Outline Layer:
  lines w10: 3389.89,3000 6207.89,3000 6207.89,6936.97 3389.89,6936.97 3389.89,3000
